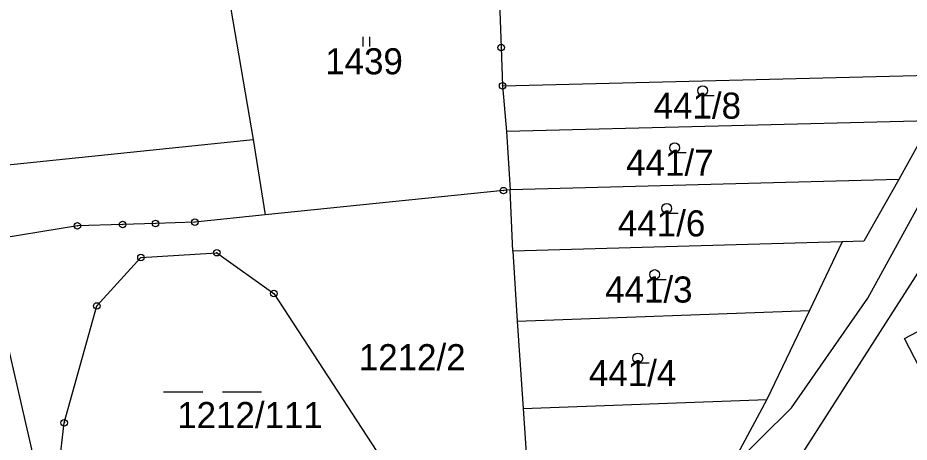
# Model space of a CAD drawing. Extents: x -564516 to -563466, y -1163913 to -1163170.
# Drawn here: x -564413.8 to -564277.2, y -1163382.1 to -1163317 of the extents above; entities that cross this region are included whole.
import ezdxf

# ---------------------------------------------------------------- set-up
doc = ezdxf.new("R2010")
doc.units = 0
for name, color, linetype in [('Hranice parcel', 7, 'Continuous'), ('Parcelní čísla', 7, 'Continuous'), ('Značky bodu BP', 7, 'Continuous'), ('Značky kultur', 7, 'Continuous')]:
    doc.layers.add(name, color=color, linetype=linetype)

msp = doc.modelspace()

# ---------------------------------------------------------------- linework, layer by layer
at = {"layer": 'Hranice parcel'}
for p, q in [((-564384.24, -1163297.26), (-564377.75, -1163335.67)), ((-564339.51, -1163327.45), (-564338.9, -1163334.47)), ((-564273.86, -1163332.84), (-564338.9, -1163334.47)), ((-564273.86, -1163332.84), (-564278.79, -1163341.81)), ((-564338.9, -1163334.47), (-564338.36, -1163343.43)), ((-564415.82, -1163339.6), (-564377.75, -1163335.67)), ((-564377.75, -1163335.67), (-564375.89, -1163347.26)), ((-564278.79, -1163341.81), (-564338.36, -1163343.43)), ((-564337.96, -1163352.84), (-564338.36, -1163343.43)), ((-564287.48, -1163351.39), (-564337.96, -1163352.84)), ((-564287.48, -1163351.39), (-564292.5, -1163361.92)), ((-564337.96, -1163352.84), (-564337.26, -1163363.54)), ((-564337.26, -1163363.54), (-564292.5, -1163361.92)), ((-564292.5, -1163361.92), (-564299.02, -1163375.58)), ((-564337.26, -1163363.54), (-564336.38, -1163376.93)), ((-564336.38, -1163376.93), (-564299.02, -1163375.58)), ((-564299.02, -1163375.58), (-564304.77, -1163386.26)), ((-564336.38, -1163376.93), (-564334.4, -1163406.5))]:
    msp.add_line(p, q, dxfattribs=at)
for points in [[(-564304.77, -1163386.26), (-564295.23, -1163376.85), (-564283.56, -1163360.04), (-564247.75, -1163294.75)], [(-564340.65, -1163296.46), (-564339.73, -1163321.6), (-564339.51, -1163327.45)], [(-564339.51, -1163327.45), (-564270.01, -1163325.7), (-564273.86, -1163332.84)], [(-564278.79, -1163341.81), (-564284.18, -1163351.3), (-564287.48, -1163351.39)], [(-564338.36, -1163343.43), (-564339.39, -1163343.53), (-564375.89, -1163347.26)], [(-564375.89, -1163347.26), (-564386.66, -1163348.36), (-564392.67, -1163348.57), (-564397.72, -1163348.74), (-564404.66, -1163348.94), (-564419.03, -1163351.27), (-564410.33, -1163389.23), (-564409.72, -1163391.93), (-564407.26, -1163410.87)], [(-564406.11, -1163409.91), (-564408.05, -1163391.13), (-564406.67, -1163379.14), (-564401.67, -1163361.22), (-564394.92, -1163353.8), (-564383.29, -1163353.05), (-564374.57, -1163359.32), (-564355.03, -1163389.25)], [(-564274.65, -1163354.2), (-564298.1, -1163390.87), (-564297.75, -1163391.1)], [(-564277.95, -1163366.22), (-564269.69, -1163361.87), (-564267.9, -1163365.27), (-564267.12, -1163364.86), (-564266.79, -1163365.47), (-564267.58, -1163365.89), (-564266.26, -1163368.4), (-564268.84, -1163369.75), (-564269.94, -1163367.65), (-564275.63, -1163370.64), (-564277.95, -1163366.22)]]:
    msp.add_lwpolyline(points, dxfattribs=at)
at = {"layer": 'Značky bodu BP'}
for centre, radius in [((-564339.73, -1163321.6), 0.5), ((-564339.73, -1163321.6), 0.0303), ((-564339.51, -1163327.45), 0.5), ((-564339.51, -1163327.45), 0.0303), ((-564339.39, -1163343.53), 0.5), ((-564339.39, -1163343.53), 0.0303), ((-564392.67, -1163348.57), 0.5), ((-564386.66, -1163348.36), 0.5), ((-564404.66, -1163348.94), 0.5), ((-564404.66, -1163348.94), 0.0303), ((-564397.72, -1163348.74), 0.5), ((-564397.72, -1163348.74), 0.0303), ((-564392.67, -1163348.57), 0.0303), ((-564386.66, -1163348.36), 0.0303), ((-564394.92, -1163353.8), 0.5), ((-564383.29, -1163353.05), 0.5), ((-564383.29, -1163353.05), 0.0303), ((-564394.92, -1163353.8), 0.0303), ((-564374.57, -1163359.32), 0.5), ((-564374.57, -1163359.32), 0.0303), ((-564401.67, -1163361.22), 0.5), ((-564401.67, -1163361.22), 0.0303), ((-564406.67, -1163379.14), 0.5), ((-564406.67, -1163379.14), 0.0303)]:
    msp.add_circle(centre, radius, dxfattribs=at)
at = {"layer": 'Značky kultur'}
for p, q in [((-564360.85, -1163321.42), (-564360.85, -1163319.92)), ((-564359.85, -1163321.42), (-564359.85, -1163319.92)), ((-564308.86, -1163328.94), (-564307.11, -1163328.94)), ((-564313.14, -1163337.7), (-564311.39, -1163337.7)), ((-564314.36, -1163347), (-564312.61, -1163347)), ((-564316.2, -1163357.15), (-564314.45, -1163357.15)), ((-564318.8, -1163369.97), (-564317.05, -1163369.97)), ((-564391.44, -1163374.4), (-564385.44, -1163374.4)), ((-564382.44, -1163374.4), (-564376.44, -1163374.4))]:
    msp.add_line(p, q, dxfattribs=at)
for centre in [(-564308.86, -1163328.19), (-564313.14, -1163336.95), (-564314.36, -1163346.25), (-564316.2, -1163356.4), (-564318.8, -1163369.22)]:
    msp.add_circle(centre, 0.75, dxfattribs=at)

# ---------------------------------------------------------------- texts
at = {"layer": 'Parcelní čísla'}
for s, p in [('1439', (-564366.69, -1163325.69)), ('441/8', (-564316.37, -1163332.49)), ('441/7', (-564320.57, -1163341.25)), ('441/6', (-564321.84, -1163350.55)), ('441/3', (-564323.8, -1163360.7)), ('1212/2', (-564361.54, -1163371.08)), ('441/4', (-564326.28, -1163373.52)), ('1212/111', (-564389.36, -1163379.96))]:
    msp.add_text(s, height=4, dxfattribs=at).set_placement(p)

doc.saveas('drawing.dxf')
